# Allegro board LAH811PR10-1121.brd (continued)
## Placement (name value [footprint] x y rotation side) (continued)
CW123  0.1U_0201_10V6K  [C_0201]  260.14 11.98 0 top
CW125  0.1U_0201_10V6K  [C_0201]  260.19 13.37 90 top
CW126  1U_0201_6.3V6M  [C_0201]  260.77 13.37 90 top
CW223  100P_0201_50V8J  [C_0201]  266.52 15.92 0 top
CW225  100P_0201_50V8J  [C_0201]  23.99 25.91 90 bottom
CW226  100P_0201_50V8J  [C_0201]  265.2 17.52 0 top
CW227  100P_0201_50V8J  [C_0201]  24.88 26.5 270 bottom
CW228  0.1U_0201_10V6K  [C_0201]  267.91 9.82 180 top
CZ1  1U_0201_6.3V6M  [C_0201]  91.25 66.06 0 bottom
CZ2  0.1U_0201_10V6K  [C_0201]  125.03 66.46 180 top
CZ3  10U_0402_10V6M  [C_0402]  107.28 72.51 0 bottom
D1  -  [BAT54CW_SOT323-3]  100.02 69.64 90 bottom
D2  -  [BAT54CW_SOT323-3]  205.09 17.49 0 bottom
D3  -  [BAT54CW_SOT323-3]  201.89 22.93 0 bottom
D12  -  [RB751V40_SC76-2]  232.33 6.14 180 bottom
D13  AZ5B75-01B.R7G_CSP0603P2Y2  [AZ5B75-01BPR7G_CSP0603P2Y2]  264.38 42.44 180 bottom
D14  AZ5B75-01B.R7G_CSP0603P2Y2  [AZ5B75-01BPR7G_CSP0603P2Y2]  265.06 42.44 0 bottom
D16  -  [TVNST52302AB0_SOT523-3]  269.89 42.87 270 bottom
D20  -  [RB751S40T1G_SOD523-2]  187.08 29.18 180 top
D21  -  [RB751S40T1G_SOD523-2]  181.8 40.61 90 bottom
D23  -  [BAT54CW_SOT323-3]  200.94 14.89 180 bottom
D75  PESD5V0H1BSF_SOD962-2-2  [ESD101-B1-02ELS_TSSLP-2-4-2]  10.43 69.33 180 bottom
D76  PESD5V0H1BSF_SOD962-2-2  [ESD101-B1-02ELS_TSSLP-2-4-2]  13.68 70.55 180 top
D77  PESD5V0H1BSF_SOD962-2-2  [ESD101-B1-02ELS_TSSLP-2-4-2]  11.06 69.33 0 bottom
D78  PESD5V0H1BSF_SOD962-2-2  [ESD101-B1-02ELS_TSSLP-2-4-2]  12.28 70.55 0 top
D79  PESD5V0H1BSF_SOD962-2-2  [ESD101-B1-02ELS_TSSLP-2-4-2]  10.38 70.55 180 top
D80  PESD5V0H1BSF_SOD962-2-2  [ESD101-B1-02ELS_TSSLP-2-4-2]  13.68 70.55 180 bottom
D81  PESD5V0H1BSF_SOD962-2-2  [ESD101-B1-02ELS_TSSLP-2-4-2]  11.01 70.55 0 top
D82  PESD5V0H1BSF_SOD962-2-2  [ESD101-B1-02ELS_TSSLP-2-4-2]  12.28 70.55 0 bottom
D83  PESD5V0H1BSF_SOD962-2-2  [ESD101-B1-02ELS_TSSLP-2-4-2]  279.34 67.71 90 bottom
D84  PESD5V0H1BSF_SOD962-2-2  [ESD101-B1-02ELS_TSSLP-2-4-2]  280.51 61.92 90 top
D85  PESD5V0H1BSF_SOD962-2-2  [ESD101-B1-02ELS_TSSLP-2-4-2]  279.34 67.07 270 bottom
D86  PESD5V0H1BSF_SOD962-2-2  [ESD101-B1-02ELS_TSSLP-2-4-2]  280.51 63.31 270 top
D87  PESD5V0H1BSF_SOD962-2-2  [ESD101-B1-02ELS_TSSLP-2-4-2]  280.48 67.71 90 top
D88  PESD5V0H1BSF_SOD962-2-2  [ESD101-B1-02ELS_TSSLP-2-4-2]  280.51 61.92 90 bottom
D89  PESD5V0H1BSF_SOD962-2-2  [ESD101-B1-02ELS_TSSLP-2-4-2]  280.48 67.07 270 top
D90  PESD5V0H1BSF_SOD962-2-2  [ESD101-B1-02ELS_TSSLP-2-4-2]  280.51 63.31 270 bottom
D116  RB751S40T1G_SOD523-2  [RB520SM-30T2R_EMD2-2]  199.94 21.73 270 bottom
D132  -  [RB751V40_SC76-2]  71.38 6.16 0 bottom
D407  AZ5B75-01B.R7G_CSP0603P2Y2  [AZ5B75-01BPR7G_CSP0603P2Y2]  12.54 67.8 270 bottom
D408  AZ5B75-01B.R7G_CSP0603P2Y2  [AZ5B75-01BPR7G_CSP0603P2Y2]  12.54 68.86 270 bottom
D409  AZ5B75-01B.R7G_CSP0603P2Y2  [AZ5B75-01BPR7G_CSP0603P2Y2]  11.01 76.59 90 top
D410  AZ5B75-01B.R7G_CSP0603P2Y2  [AZ5B75-01BPR7G_CSP0603P2Y2]  11.01 75.44 90 top
D411  AZ5B75-01B.R7G_CSP0603P2Y2  [AZ5B75-01BPR7G_CSP0603P2Y2]  10.94 74.68 0 top
D412  AZ5B75-01B.R7G_CSP0603P2Y2  [AZ5B75-01BPR7G_CSP0603P2Y2]  11.33 68.52 180 top
D413  AZ5B75-01B.R7G_CSP0603P2Y2  [AZ5B75-01BPR7G_CSP0603P2Y2]  10.06 68.52 180 top
D414  AZ5B75-01B.R7G_CSP0603P2Y2  [AZ5B75-01BPR7G_CSP0603P2Y2]  11.01 78.12 270 top
D415  AZ5B75-01B.R7G_CSP0603P2Y2  [AZ5B75-01BPR7G_CSP0603P2Y2]  280.48 65.26 90 bottom
D416  AZ5B75-01B.R7G_CSP0603P2Y2  [AZ5B75-01BPR7G_CSP0603P2Y2]  280.48 64.18 90 bottom
D417  AZ5B75-01B.R7G_CSP0603P2Y2  [AZ5B75-01BPR7G_CSP0603P2Y2]  281.35 64.59 270 top
D418  AZ5B75-01B.R7G_CSP0603P2Y2  [AZ5B75-01BPR7G_CSP0603P2Y2]  281.35 65.67 270 top
D419  AZ5B75-01B.R7G_CSP0603P2Y2  [AZ5B75-01BPR7G_CSP0603P2Y2]  276.57 57.09 90 bottom
D420  AZ5B75-01B.R7G_CSP0603P2Y2  [AZ5B75-01BPR7G_CSP0603P2Y2]  279.24 66.24 180 top
D421  AZ5B75-01B.R7G_CSP0603P2Y2  [AZ5B75-01BPR7G_CSP0603P2Y2]  278.86 63.7 0 top
D422  AZ5B75-01B.R7G_CSP0603P2Y2  [AZ5B75-01BPR7G_CSP0603P2Y2]  276.57 58.23 90 bottom
D438  -  [RB751S40T1G_SOD523-2]  175.05 10.71 180 top
D459  AZ4520-01F.R7G_DFN1610P2E2  [AZ4520-01FPR7G_DFN1610P2E2]  11.8 64.97 0 bottom
D460  AZ4520-01F.R7G_DFN1610P2E2  [AZ4520-01FPR7G_DFN1610P2E2]  281.65 60.04 90 bottom
D461  SDM2U30CSP-7B  [NSR20F30NXT5G_DSN2-2]  31.73 27.17 0 bottom
D462  SDM2U30CSP-7B  [NSR20F30NXT5G_DSN2-2]  259.67 29.55 180 top
D465  PESD5V0H1BSF_SOD962-2-2  [ESD101-B1-02ELS_TSSLP-2-4-2]  127.22 61.49 90 top
D466  PESD5V0H1BSF_SOD962-2-2  [ESD101-B1-02ELS_TSSLP-2-4-2]  126.58 65.58 0 top
D468  -  [RB751S40T1G_SOD523-2]  172.34 51.38 0 top
D469  -  [LNZ8F6V2T5G_SOD882-2-X]  59.15 12.01 45 bottom
D470  -  [LNZ8F6V2T5G_SOD882-2-X]  228.77 16.63 90 bottom
D471  PESD5V0H1BSF_SOD962-2-2  [ESD101-B1-02ELS_TSSLP-2-4-2]  126.07 62.76 0 top
D474  -  [RB751S40T1G_SOD523-2]  173.48 9.44 0 top
D475  -  [RB751S40T1G_SOD523-2]  173.48 8.17 0 top
D481  -  [RB751V40_SC76-2]  222.92 13.51 0 bottom
D482  -  [TVNST52302AB0_SOT523-3]  197.19 5.11 270 bottom
D483  -  [TVNST52302AB0_SOT523-3]  197.28 2.62 270 bottom
D484  AZ5B75-01B.R7G_CSP0603P2Y2  [AZ5B75-01BPR7G_CSP0603P2Y2]  158.33 65.09 180 top
D485  AZ5B75-01B.R7G_CSP0603P2Y2  [AZ5B75-01BPR7G_CSP0603P2Y2]  159.09 65.09 0 top
D486  PESD5V0H1BSF_SOD962-2-2  [ESD101-B1-02ELS_TSSLP-2-4-2]  128.17 62.53 180 top
D487  -  [RB751S40T1G_SOD523-2]  173.18 11.96 180 top
DA1  -  [ESD207-B1-02EL_TSLP-2-19-2]  276.19 66.24 0 bottom
DA3  -  [ESD207-B1-02EL_TSLP-2-19-2]  274.59 61.66 270 bottom
DA4  -  [ESD207-B1-02EL_TSLP-2-19-2]  270.6 61.66 270 bottom
DA5  -  [ESD207-B1-02EL_TSLP-2-19-2]  266.41 61.69 270 bottom
DA8  AZ4A24-01F.R7G_DFN0603P2Y2  [AZ4A24-01FPR7G_DFN0603P2Y2]  20.03 32.23 90 top
DA9  AZ4A24-01F.R7G_DFN0603P2Y2  [AZ4A24-01FPR7G_DFN0603P2Y2]  20.03 34.48 270 top
DA10  -  [RB751S40T1G_SOD523-2]  266.66 54.81 90 top
DA11  AZ5125-01H.R7G_SOD523-2  [AZ5125-01HPR7G_SOD523-2]  255.61 60.9 180 bottom
DA13  -  [ESD207-B1-02EL_TSLP-2-19-2]  276.17 69.33 180 bottom
DA14  AZ4A24-01F.R7G_DFN0603P2Y2  [AZ4A24-01FPR7G_DFN0603P2Y2]  268.82 33.87 270 bottom
DA15  AZ4A24-01F.R7G_DFN0603P2Y2  [AZ4A24-01FPR7G_DFN0603P2Y2]  268.82 31.22 90 bottom
DA16  -  [ESD207-B1-02EL_TSLP-2-19-2]  24.1 27.32 0 bottom
DA17  -  [ESD207-B1-02EL_TSLP-2-19-2]  23.2 25.72 270 bottom
DA18  -  [ESD207-B1-02EL_TSLP-2-19-2]  266.72 17.67 0 top
DA19  -  [ESD207-B1-02EL_TSLP-2-19-2]  259.55 9.92 180 top
DC1  RB751S40T1G_SOD523-2  [RB520SM-30T2R_EMD2-2]  175.34 31.39 270 bottom
DC2  RB751S40T1G_SOD523-2  [RB520SM-30T2R_EMD2-2]  176.62 29.15 90 bottom
DE1  -  [RB520SM-30T2R_EMD2-2]  190.06 2.72 90 top
DE3  -  [RB520SM-30T2R_EMD2-2]  191.78 2.93 90 top
DR1  0_0402_5%  [R_0402]  248.43 9.95 0 bottom
DR2  0_0402_5%  [R_0402]  248.43 10.74 0 bottom
DR3  0_0402_5%  [R_0402]  268.25 10.71 180 top
DR6  0_0402_5%  [R_0402]  267.33 14.44 0 top
DR7  0_0402_5%  [R_0402]  267.33 15.26 0 top
DR8  0_0402_5%  [R_0402]  264.83 16.83 270 top
DR9  0_0402_5%  [R_0402]  268.25 11.52 180 top
DR10  0_0402_5%  [R_0402]  263.31 16.6 270 top
DR11  0_0402_5%  [R_0402]  262.55 16.54 270 top
DR12  0_0402_5%  [R_0402]  268.26 13.63 180 top
DR13  0_0402_5%  [R_0402]  245.35 10.05 0 bottom
DR14  33_0402_1%  [R_0402]  265.85 20.08 270 top
DR15  33_0402_1%  [R_0402]  266.69 20.08 270 top
DR16  33_0402_1%  [R_0402]  259.42 15.33 0 top
DR17  33_0402_1%  [R_0402]  258.61 12.18 90 top
DR18  0_0402_5%  [R_0402]  255.74 22.95 270 bottom
DR19  0_0402_5%  [R_0402]  256.53 22.95 270 bottom
DT1  -  [1N4148WS-L_SOD323-2]  28.28 63.57 0 bottom
DT2  -  [1N4148WS-L_SOD323-2]  282.51 52.75 90 bottom
DV11  RB751S40T1G_SOD523-2  [RB520SM-30T2R_EMD2-2]  108.9 68.06 270 bottom
DV12  RB751S40T1G_SOD523-2  [RB520SM-30T2R_EMD2-2]  114.64 68.13 90 bottom
DZ3  -  [RB751S40T1G_SOD523-2]  244.48 8.96 0 bottom
DZ4  -  [RB751S40T1G_SOD523-2]  244.45 11.07 0 bottom
F1  0.5A_65V_T0603FF0500TM  [F_T0603FF0500TM]  162.7 65.73 180 top
F2  0.5A_32V_0438.500WR  [F_0438P500WR]  256.43 42.82 270 bottom
F3  3A_32V_F0603FA3000V032T  [F_F0603FA3000V032T]  96.64 71.94 270 bottom
F5  0.5A_65V_T0603FF0500TM  [F_T0603FF0500TM]  160.67 62.98 90 top
F6  0.5A_65V_T0603FF0500TM  [F_T0603FF0500TM]  165.95 62.58 90 top
FD1  -  [FIDUCIAL_C40M80]  19.39 61.66 0 top
FD2  -  [FIDUCIAL_C40M80]  272.71 24.71 0 top
FD3  -  [FIDUCIAL_C40M80]  42.74 9.82 180 bottom
FD4  -  [FIDUCIAL_C40M80]  257.75 67.58 180 bottom
FD5  -  [FIDUCIAL_C40M80]  272.66 8.45 180 bottom
H1  -  [H_1P6]  11.6 82.85 45 top
H2  H_3P6  [H_3P6-G]  4.85 67.7 90 top
H4  H_2P6  [H_2P6-G]  40.46 27.84 0 top
H5  H_3P6  [H_3P6-G]  19.9 2.8 0 top
H6  H_3P6  [H_3P6-G]  88.95 55.22 0 top
H7  H_3P6  [H_3P6-G]  203.95 55.22 0 top
H8  H_3P6  [H_3P6-G]  273 2.8 0 top
H9  H_2P6  [H_2P6-G]  254.6 32.34 0 top
H10  H_3P6  [H_3P6-G]  287.06 54.64 0 top
H14  -  [H_1P3N]  1.55 44.9 0 top
H15  PAD~50  [TPC20]  196.27 10.71 180 bottom
H16  PAD~50  [TPC20]  261.39 2.73 180 bottom
H18  PAD~50  [TPC20]  120.35 66.4 180 bottom
H19  PAD~50  [TPC20]  146.45 65.7 180 bottom
H20  PAD~50  [TPC20]  172.55 66.4 180 bottom
HCPU1  -  [H_3P3]  114.31 63.52 0 top
HCPU2  -  [H_3P3]  113.87 36.32 0 top
HCPU3  -  [H_3P3]  179.02 36.32 0 top
HCPU4  -  [H_3P3]  178.59 63.52 0 top
HSSD1  -  [H_3P3]  105.29 17.15 0 top
JAPS1  ACES_50506-01841-P01  [ACES_50506-01841-P01_18P]  194.27 21.35 90 top
JBATT1  DEREN_40-42507-01001RHF_10P  [DEREN_40-42507-01001RHF_10P-T]  44.03 24.06 225 bottom
JDB1  ACES_50521-01041-P01  [ACES_50521-01041-P01_10P]  34.4 33.76 90 top
JDB2  ACES_50521-01041-P01  [ACES_50521-01041-P01_10P]  279 46.08 90 top
JDB3  JXT_FP241AH-006GAAM  [JXT_FP241AH-006GAAM_6P]  33.66 56.48 90 top
JDB4  JXT_FP241AH-006GAAM  [JXT_FP241AH-006GAAM_6P]  278.39 40.47 90 top
JDEBUG1  ACES_50521-01041-P01  [ACES_50521-01041-P01_10P]  193.4 44.68 90 top
JDEBUG2  ACES_50521-01041-P01  [ACES_50521-01041-P01_10P]  151.01 6.07 0 top
JDEG1  -  [ACES_50521-01041-P01_10P]  238.61 13.78 0 bottom
JEDP1  I-PEX_20698-042E-01  [I-PEX_20698-042E-01_42P-T]  134.7 64.33 180 bottom
JFAN1  ACES_50224-00401-001  [ACES_50224-00401-001_4P]  65.95 6.77 0 bottom
JFAN2  ACES_50224-00401-001  [ACES_50224-00401-001_4P]  232.15 7.98 0 bottom
JFP1  TWVM_FPC0510-08RC-TAGHA  [TWVM_FPC0510-08RC-TAGHA_8P]  256.95 36.94 270 bottom
JHP1  UNIMI_FCECBE015  [UNIMI_FCECBE015_6P-T]  268.2 66.61 180 bottom
JIO1  HRS_FH35C-45S-0P3SHW(50)  [HRS_FH35C-45S-0P3SHW-50_45P]  215.15 8.23 180 bottom
JMIPI60  SAMTE_QSH-030-01-L-D-A  [SAMTE_QSH-030-01-H-D-A_60P-T]  90.88 65.78 0 top
JNGFF1  LOTES_APCI0146-P004A  [LOTES_APCI0146-P004A_75P]  188.83 7.9 90 bottom
JP1  T-SOL_5-751903001000-6  [T-SOL_5-751903001000-6_22P-T]  0.5 48.05 90 bottom
JSPI1  -  [ACES_50521-01041-P01_10P]  193.66 35.53 270 bottom
JSPK1  ACES_50208-0040C-P03  [ACES_50208-0040C-P03_4P-T]  19.24 32.6 90 bottom
JSPK2  ACES_50208-0040C-P03  [ACES_50208-0040C-P03_4P-T]  270.67 32.8 270 bottom
JTAG2  @SHORT PADS~D  [SHORTPADS]  189.57 8.88 0 top
JTP1  ACES_50506-00841-P01  [ACES_50506-00841-P01_8P]  206.21 10.06 180 bottom
JUART1  CVILU_CI1804M1VRA-NH  [CVILU_CI1804M1VRA-NH_4P]  179.49 42.3 270 top
JUFC1  I-PEX_20698-042E-01  [I-PEX_20698-042E-01_42P-T]  165.2 64.33 180 bottom
JUSBC1  DEREN_560Q10-002H  [DEREN_560Q10-002H_24P-T]  9.67 74.08 90 bottom
JUSBC2  DEREN_560Q10-002H  [DEREN_560Q10-002H_24P-T]  283.22 68.15 270 bottom
JWLA1  TWVM_FPC0511-04RC-TAGHT  [TWVM_FPC0511-04RC-TAGHT_4P]  264.88 13.15 270 bottom
JWLA2  TWVM_FPC0511-04RC-TAGHT  [TWVM_FPC0511-04RC-TAGHT_4P]  21.24 30.01 180 bottom
L12  BLM15PX330SN1D_2P  [MURAT_BLM15PX330SN1D_2P]  275.65 68.18 270 bottom
L15  BLM15PX330SN1D_2P  [MURAT_BLM15PX330SN1D_2P]  271.57 61.64 0 bottom
L71  BLM15PX330SN1D_2P  [MURAT_BLM15PX330SN1D_2P]  265.7 15.93 90 top
L72  BLM15PX330SN1D_2P  [MURAT_BLM15PX330SN1D_2P]  267.44 16.73 180 top
L73  BLM15PX330SN1D_2P  [MURAT_BLM15PX330SN1D_2P]  25.03 23.9 90 bottom
L74  BLM15PX330SN1D_2P  [MURAT_BLM15PX330SN1D_2P]  24.14 23.9 90 bottom
LA1  HCB2012KF-600T30  [TAI-T_HCB2012KF-121T50_2P]  257.27 62.93 270 bottom
LA18  BLM15AX700SN1D_2P  [MURAT_BLM15AX700SN1D_2P]  263.74 66.87 270 bottom
LA19  BLM15AX700SN1D_2P  [MURAT_BLM15AX700SN1D_2P]  263.74 65.09 270 bottom
LA20  BLM15AX700SN1D_2P  [MURAT_BLM15AX700SN1D_2P]  23.93 27.45 180 top
LA21  BLM15AX700SN1D_2P  [MURAT_BLM15AX700SN1D_2P]  25.74 27.4 90 top
LA22  BLM15AX700SN1D_2P  [MURAT_BLM15AX700SN1D_2P]  267.37 31.44 270 top
LA23  BLM15AX700SN1D_2P  [MURAT_BLM15AX700SN1D_2P]  269.94 37.36 90 top
LC1  0.68UH_UHP252012NF-R68M_3A_20%  [TAI-T_UHP252012NF-R68M_2P]  174.77 49.5 0 bottom
LC2  BLM18EG221TN1D_2P~D  [MURAT_BLM18EG221SN1D_2P]  175.43 44.7 180 bottom
LED1  HT-F196BP5_WHITE  [LED_HT-F196BP5_2P]  252.87 22.43 90 bottom
LED2  HT-F196BP5_WHITE  [LED_HT-F196BP5_2P]  251.63 22.43 90 bottom
LT3  BLM18KG331SN1D_2P  [MURAT_BLM18KG331SN1D_2P]  25.89 46.05 0 bottom
LT5  0.68UH_MLV-YT10NR68N-M1L_2.7A_30%  [MAG_MLV-YT10NR68N-M1L_2P]  265.01 47.85 180 bottom
LT8  0.68UH_MLV-YT10NR68N-M1L_2.7A_30%  [MAG_MLV-YT10NR68N-M1L_2P]  22.47 53.1 270 bottom
LT9  HCB2012KF-800T50_2P  [TAI-T_HCB2012KF-121T50_2P]  61.85 9.69 315 bottom
LT10  HCB2012KF-800T50_2P  [TAI-T_HCB2012KF-121T50_2P]  237.73 6.18 90 bottom
LT11  HCB2012KF-800T50_2P  [TAI-T_HCB2012KF-121T50_2P]  28.04 25.23 0 bottom
LT12  HCB2012KF-800T50_2P  [TAI-T_HCB2012KF-121T50_2P]  262.36 25.8 180 top
LT13  HCB2012KF-800T50_2P  [TAI-T_HCB2012KF-121T50_2P]  28.04 23.46 0 bottom
LT14  HCB2012KF-800T50_2P  [TAI-T_HCB2012KF-121T50_2P]  262.36 27.58 180 top
LT15  BLM18KG331SN1D_2P  [MURAT_BLM18KG331SN1D_2P]  258.41 48.58 0 top
LV1  BLM15PX221SN1D_2P  [MURAT_BLM15PX221SN1D_2P]  135.74 64.28 180 top
ML1  HCM1012GH900BP_4P  [INPAQ_HCM1012GH900BP_4P]  256.93 19.83 0 top
ML6  HCM1012GH900BP_4P  [INPAQ_HCM1012GH900BP_4P]  14.81 68.39 180 bottom
ML7  HCM1012GH900BP_4P  [INPAQ_HCM1012GH900BP_4P]  11.75 72.44 90 top
ML16  HCM1012GH900BP_4P  [INPAQ_HCM1012GH900BP_4P]  278.22 64.61 0 bottom
ML17  HCM1012GH900BP_4P  [INPAQ_HCM1012GH900BP_4P]  279.13 65.15 0 top
ML18  HCM1012GH900BP_4P  [INPAQ_HCM1012GH900BP_4P]  267.96 43.07 180 bottom
NOREF  -  []  202.91 4.77 0 top
NOREF#2  -  []  83.96 11.28 0 top
NOREF#3  -  []  102.5 47.26 90 top
NOREF#4  -  []  170.78 -19.36 0 top
NOREF#5  -  []  214.09 4.07 0 top
NOREF#6  -  []  104.74 -40.32 0 top
NOREF#7  -  []  195.49 59.15 0 top
NOREF#8  -  []  22.37 13.2 0 top
NOREF#9  -  []  116.1 40.52 0 top
NOREF#10  -  []  110.78 1.58 180 bottom
PC132  0.01UF_0402_25V7K  [C_0402]  61.35 17.85 0 bottom
PC133  100P_0201_50V8J  [C_0201]  61.69 17.09 0 bottom
PC134  1000P_0201_50V7K  [C_0201]  52.23 19.55 45 bottom
PC135  100P_0201_50V8J  [C_0201]  51.75 20 45 bottom
PC200  0.1U_0402_25V6  [C_0402]  78.96 11.04 90 bottom
PC201  0.1U_0402_25V6  [C_0402]  72.47 14.17 180 bottom
PC202  2200P_0402_50V7K  [C_0402]  78.96 13.86 270 bottom
PC203  10U_0603_25V6M  [C_0603-H1_2]  80.05 14 270 bottom
PC204  10U_0603-H1_2_25V6M  [C_0603-H1_2]  72.28 13.21 270 bottom
PC207  10U_0603-H1_2_25V6M  [C_0603-H1_2]  78.03 18.76 180 bottom
PC210  4.7U_0402_16V6M  [C_0402]  36.77 6.11 90 bottom
PC211  0.1U_0402_25V6  [C_0402]  40.68 4.03 90 top
PC212  1U_0402_25V6K  [C_0402]  34.58 2.91 270 bottom
PC213  1U_0402_25V6K  [C_0402]  37.02 2.91 0 bottom
PC214  10U_0603_25V6M  [C_0603]  93.69 28.2 90 top
PC215  10U_0603_25V6M  [C_0603]  90.07 20.64 0 top
PC216  10U_0603_25V6M  [C_0603]  93.42 25.32 0 bottom
PC217  10U_0603-H1_2_25V6M  [C_0603-H1_2]  90.07 21.91 0 bottom
PC218  33U_B3_16VM_R45M  [C_B3]  80.72 25.17 315 bottom
PC219  33U_B3_16VM_R45M  [C_B3]  83.04 27.49 315 bottom
PC221  10U_0603-H1_2_25V6M  [C_0603-H1_2]  91.78 25.53 270 bottom
PC222  10U_0603-H1_2_25V6M  [C_0603-H1_2]  90.07 20.64 0 bottom
PC223  0.1U_0402_25V6  [C_0402]  93.38 26.41 0 bottom
PC224  2200P_0402_50V7K  [C_0402]  94.44 25.17 0 top
PC225  0.47U_0603_25V7K  [C_0603]  39 8.69 270 bottom
PC226  1U_0402_25V6K  [C_0402]  37.68 5.22 90 bottom
PC227  4.7U_0603_25VAK  [C_0603]  36.54 4.62 180 bottom
PC228  2.2U_0402_6.3V6M  [C_0402]  35.27 9.83 180 top
PC229  2.2U_0402_6.3V6M  [C_0402]  33.31 4.64 0 bottom
PC230  0.47U_0603_25V7K  [C_0603]  33.53 11.66 135 bottom
PC231  10U_0603_25V6M  [C_0603]  72.78 17.61 270 bottom
PC232  10U_0603_25V6M  [C_0603]  71.51 16.6 270 bottom
PC233  4700P_0402_25V7K  [C_0402]  63.03 12.64 180 bottom
PC234  2200P_0402_50V7K  [C_0402]  58.78 13.22 225 bottom
PC235  2.2U_0402_25V6M  [C_0402]  32.19 11.45 135 bottom
PC236  680P_0402_50V7K  [C_0402]  79.59 8.58 90 bottom
PC237  680P_0402_50V7K  [C_0402]  92.6 13.66 0 bottom
PC238  1U_0402_25V6K  [C_0402]  33.94 17.61 270 bottom
PC239  1U_0402_25V6K  [C_0402]  33.68 15.81 180 bottom
PC240  0.22U_0402_25V6K  [C_0402]  32.86 16.69 90 bottom
PC241  560P_0402_50V7K  [C_0402]  30.35 8.37 90 bottom
PC243  0.01U_0402_16V7K  [C_0402]  29.48 8.41 180 bottom
PC244  0.1U_0402_25V6  [C_0402]  28.7 9.82 180 bottom
PC245  0.1U_0402_25V6  [C_0402]  30.39 10.66 90 bottom
PC246  15U_B2_25VM_R100M  [C_B2]  74.59 13.58 90 bottom
PC247  15U_B2_25VM_R100M  [C_B2]  77.11 16.55 0 bottom
PC249  1U_0201_6.3V6M  [C_0201]  36.37 9.06 0 top
PC335  1U_0402_16V6K  [C_0402]  218.45 20.06 270 bottom
PC336  2200P_0402_50V7K  [C_0402]  203.8 26.87 225 bottom
PC337  0.1U_0402_25V6  [C_0402]  216.32 15.49 0 bottom
PC338  22U_0603_6.3V6M  [C_0603-H1_2]  206.21 32.2 45 bottom
PC339  2200P_0402_50V7K  [C_0402]  207.86 30.17 45 bottom
PC340  2200P_0402_50V7K  [C_0402]  216.32 16.43 0 bottom
PC341  680P_0603_50V7K  [C_0603]  206.59 21.4 135 bottom
PC342  4.7U_0402_6.3V6M  [C_0402]  211.77 18.79 0 bottom
PC343  0.22U_0402_16V7K  [C_0402]  214.8 21.99 225 bottom
PC344  22U_0603_6.3V6M  [C_0603-H1_2]  204.81 34.36 45 bottom
PC345  10U_0603_25V6M  [C_0603-H1_2]  212.56 15.63 90 bottom
PC346  22U_0603_6.3V6M  [C_0603-H1_2]  205.7 33.47 45 bottom
PC347  22U_0603_6.3V6M  [C_0603-H1_2]  202.4 28.9 225 bottom
PC348  22U_0603_6.3V6M  [C_0603-H1_2]  206.85 30.93 45 bottom
PC349  10U_0603_25V6M  [C_0603-H1_2]  215.42 16.35 180 bottom
PC350  22U_0603_6.3V6M  [C_0603-H1_2]  203.31 28.05 225 bottom
PC351  22U_0603_6.3V6M  [C_0603-H1_2]  204.06 25.32 270 bottom
PC400  0.22U_0402_16V7K  [C_0402]  21.67 15.53 180 bottom
PC401  0.1U_0402_25V6  [C_0402]  31.32 14.01 270 bottom
PC402  2200P_0402_50V7K  [C_0402]  29.89 15.43 90 bottom
PC403  10U_0603_25V6M  [C_0603-H1_2]  30.42 17.47 180 bottom
PC404  10U_0603_25V6M  [C_0603-H1_2]  30.27 14.01 270 bottom
PC405  220P_0201_25V7K  [C_0201]  25.24 19.12 0 bottom
PC406  22U_0603_6.3V6M  [C_0603-H0_8]  25.08 3.97 270 top
PC407  22U_0603_6.3V6M  [C_0603-H0_8]  27.53 3.97 270 top
PC408  22U_0603_6.3V6M  [C_0603-H0_8]  25.11 3.5 270 bottom
PC409  22U_0603_6.3V6M  [C_0603-H0_8]  26.31 3.96 270 top
PC410  22U_0603_6.3V6M  [C_0603-H1_2]  26.17 9.85 90 bottom
PC412  22U_0603_6.3V6M  [C_0603-H1_2]  24.95 9.85 90 bottom
PC414  2.2U_0402_6.3V6M  [C_0402]  28.75 11.48 180 bottom
PC415  680P_0603_50V7K  [C_0603]  21.74 19.37 0 top
PC416  0.22U_0402_16V7K  [C_0402]  274.08 25.34 90 bottom
PC417  0.1U_0402_25V6  [C_0402]  271.62 15.69 0 bottom
PC418  2200P_0402_50V7K  [C_0402]  271.62 16.58 0 bottom
PC419  10U_0603_25V6M  [C_0603-H1_2]  270.65 16.45 180 bottom
PC420  10U_0603_25V6M  [C_0603-H1_2]  270.65 15.23 180 bottom
PC421  220P_0201_25V7K  [C_0201]  274.38 19.58 270 top
PC422  22U_0603_6.3V6M  [C_0603-H1_2]  261.53 24.82 180 bottom
PC423  22U_0603_6.3V6M  [C_0603-H0_8]  261.53 26.06 180 bottom
PC424  22U_0603_6.3V6M  [C_0603-H1_2]  261.48 23.55 180 bottom
PC425  22U_0603_6.3V6M  [C_0603-H1_2]  263.84 24 270 bottom
PC426  22U_0603_6.3V6M  [C_0603-H1_2]  262.62 23.39 270 bottom
PC428  22U_0603_6.3V6M  [C_0603-H1_2]  261.53 27.31 180 bottom
PC430  2.2U_0402_6.3V6M  [C_0402]  268.31 18.46 90 bottom
PC431  680P_0603_50V7K  [C_0603]  271.1 19.55 180 top
PC432  33U_B3_16VM_R45M  [C_B3]  31.88 19.81 180 bottom
PC433  33U_B3_16VM_R45M  [C_B3]  267.4 16.4 180 bottom
PC500  0.22U_0402_16V7K  [C_0402]  195.61 60.25 315 bottom
PC501  10U_0603_25V6M  [C_0603]  201.62 63.75 315 top
PC502  10U_0603_25V6M  [C_0603]  201.44 63.57 315 bottom
PC503  0.1U_0402_25V6  [C_0402]  202.6 63.97 315 bottom
PC504  2200P_0402_25V7K  [C_0402]  202.03 64.58 135 bottom
PC505  220P_0201_25V7K  [C_0201]  197.93 65.37 135 bottom
PC506  22U_0603_6.3V6M  [C_0603]  194.81 47.92 180 bottom
PC507  22U_0603_6.3V6M  [C_0603]  197.16 45.48 0 bottom
PC508  22U_0603_6.3V6M  [C_0603]  194.74 46.68 180 bottom
PC509  22U_0603_6.3V6M  [C_0603]  197.16 46.7 0 bottom
PC510  2.2U_0402_6.3V6M  [C_0402]  197.38 62.61 45 bottom
PC512  680P_0603_50V7K  [C_0603]  191.98 51.21 270 bottom
PC600  4.7U_0402_6.3V6M  [C_0402]  113.33 2.56 0 top
PC700  0.22U_0402_25V6K  [C_0402]  99.71 17.09 0 bottom
PC701  680P_0603_50V7K  [C_0603]  100.04 21.15 0 bottom
PC702  220P_0402_50V8J  [C_0402]  102.2 13.35 270 bottom
PC703  22U_0603_6.3V6M  [C_0603-H1_2]  95.3 23.74 180 bottom
PC704  2200P_0402_50V7K  [C_0402]  98.67 27.2 90 bottom
PC705  22U_0603_6.3V6M  [C_0603-H1_2]  101.44 23.69 270 bottom
PC706  22U_0603_6.3V6M  [C_0603-H1_2]  100.17 23.69 270 bottom
PC707  22U_0603_6.3V6M  [C_0603-H1_2]  96.31 27.25 90 bottom
PC708  2200P_0402_50V7K  [C_0402]  95.21 27.12 90 bottom
PC709  10U_0603_25V6M  [C_0603-H1_2]  99.21 9.85 180 bottom
PC710  0.1U_0402_25V6  [C_0402]  100.6 9.72 0 bottom
PC711  2200P_0402_25V7K  [C_0402]  100.6 8.7 0 bottom
PC713  0.22U_0402_10V6K  [C_0402]  95.67 14.65 180 bottom
PC714  0.22U_0402_10V6K  [C_0402]  95.67 13.76 180 bottom
PC715  1U_0402_16V6K  [C_0402]  95.59 11.42 90 bottom
PC750  10U_0603_25V6M  [C_0603-H1_2]  99.21 8.58 180 bottom
PC751  22U_0603_6.3V6M  [C_0603-H1_2]  97.58 27.25 90 bottom
PC801  0.22U_0402_16V7K  [C_0402]  200.67 42.79 0 bottom
PC802  10U_0603_25V6M  [C_0603]  202.88 48.35 0 bottom
PC803  10U_0603_25V6M  [C_0603]  202.88 48.36 0 top
PC804  0.1U_0402_25V6  [C_0402]  203.21 49.73 0 bottom
PC805  2200P_0402_25V7K  [C_0402]  203.21 49.73 0 top
PC806  22U_0603_6.3V6M  [C_0603]  203.8 38.04 0 bottom
PC807  22U_0603_6.3V6M  [C_0603]  203.8 39.31 0 bottom
PC808  22U_0603_6.3V6M  [C_0603]  201.83 41.11 180 bottom
PC809  22U_0603_6.3V6M  [C_0603]  204.43 36.75 0 bottom
PC810  2.2U_0402_6.3V6M  [C_0402]  200.75 45.26 180 bottom
PC811  680P_0402_50V7K  [C_0402]  204.56 41.9 90 top
PC812  220P_0402_50V8J  [C_0402]  199.84 44.9 0 top
PC900  1U_0402_16VAK  [C_0402]  192.43 70.74 45 bottom
PC901  1U_0402_25V6K  [C_0402]  188.98 68.58 135 bottom
PC902  10U_0603_16VAM  [C_0603-H1_2]  195.81 70.11 135 bottom
PC903  33U_B3_16VM_R45M  [C_B3]  202.85 71.16 90 bottom
PC904  10U_0603_16VAM  [C_0603-H1_2]  196.52 69.41 315 bottom
PC905  10U_0603_25V6M  [C_0603]  195.8 70.11 135 top
PC906  10U_0603_25V6M  [C_0603]  196.69 70.96 135 top
PC907  10U_0603_25V6M  [C_0603]  196.51 69.41 315 top
PC908  10U_0603_16VAM  [C_0603-H1_2]  196.69 70.94 135 bottom
PC909  1U_0402_16VAK  [C_0402]  198.9 69.79 270 bottom
PC910  1U_0402_25V6K  [C_0402]  194.97 62.75 315 bottom
PC911  0.1U_0201_25V6K  [C_0201]  195.91 64.98 315 bottom
PC912  680P_0603_50V7K  [C_0603]  187.87 71.01 45 bottom
PC1000  150U_B3_6.3VM_R35M  [C_TEPSLB30J157M-35-8R]  184.47 56.89 225 bottom
PC1001  150U_B3_6.3VM_R35M  [C_TEPSLB30J157M-35-8R]  186.75 54.6 225 bottom
PC1004  22U_0603_6.3V6M  [C_0603-H0_8]  162.59 53.66 0 top
PC1005  22U_0603_6.3V6M  [C_0603-H0_8]  138.43 52.9 180 top
PC1006  22U_0603_6.3V6M  [C_0603-H0_8]  142.58 55.41 0 top
PC1007  22U_0603_6.3V6M  [C_0603-H0_8]  141.03 61.17 90 top
PC1008  22U_0603_6.3V6M  [C_0603-H0_8]  127.96 52.56 180 top
PC1009  22U_0603_6.3V6M  [C_0603-H0_8]  162.59 52.45 0 top
PC1010  22U_0603_6.3V6M  [C_0603-H0_8]  159.2 52.45 270 top
PC1011  22U_0603_6.3V6M  [C_0603-H0_8]  160.63 54.46 90 top
PC1012  22U_0603_6.3V6M  [C_0603-H0_8]  139.26 60 270 top
PC1013  22U_0603_6.3V6M  [C_0603-H0_8]  136.93 61.35 180 bottom
PC1014  10U_0402_6.3V6M  [C_0402]  138.75 54.56 90 top
PC1015  10U_0402_6.3V6M  [C_0402]  157.19 59.26 270 top
PC1016  10U_0402_6.3V6M  [C_0402]  158.27 60.76 90 top
PC1017  10U_0402_6.3V6M  [C_0402]  155.78 54.44 90 top
PC1018  10U_0402_6.3V6M  [C_0402]  159.57 54.4 90 top
PC1019  10U_0402_6.3V6M  [C_0402]  160.28 52.51 270 top
PC1020  10U_0402_6.3V6M  [C_0402]  156.71 54.43 90 top
PC1021  10U_0402_6.3V6M  [C_0402]  139.72 54.57 90 top
PC1022  10U_0402_6.3V6M  [C_0402]  140.07 62.55 0 bottom
PC1023  10U_0402_6.3V6M  [C_0402]  141.63 54.57 90 top
PC1024  22U_0603_6.3V6M  [C_0603-H0_8]  161.35 52.44 270 top
PC1025  22U_0603_6.3V6M  [C_0603-H0_8]  139.84 61.14 90 top
PC1026  47U_0603_6.3V6M  [C_0603-H1_2]  182.3 59.63 225 bottom
PC1027  22U_0603_6.3V6M  [C_0603-H0_8]  158.5 54.46 90 top
PC1028  22U_0603_6.3V6M  [C_0603-H0_8]  155.09 60.6 180 top
PC1029  22U_0603_6.3V6M  [C_0603-H0_8]  156.33 52.2 270 top
PC1030  47U_0603_6.3V6M  [C_0603-H1_2]  183.17 58.77 225 bottom
PC1031  10U_0402_6.3V6M  [C_0402]  156.3 59.26 270 top
PC1032  10U_0402_6.3V6M  [C_0402]  137.89 61.23 90 top
PC1033  10U_0402_6.3V6M  [C_0402]  157.39 52.51 270 top
PC1034  10U_0402_6.3V6M  [C_0402]  138.77 61.23 90 top
PC1035  10U_0402_6.3V6M  [C_0402]  129.76 53.15 0 top
PC1036  10U_0402_6.3V6M  [C_0402]  140.63 54.54 90 top
PC1037  10U_0402_6.3V6M  [C_0402]  157.38 60.76 90 top
PC1038  10U_0402_6.3V6M  [C_0402]  159.09 59.26 270 top
PC1039  10U_0402_6.3V6M  [C_0402]  137 61.23 90 top
PC1040  1U_0201_6.3V6M  [C_0201]  138.56 51.96 270 top
PC1041  1U_0201_6.3V6M  [C_0201]  138.39 61.07 90 bottom
PC1042  1U_0201_6.3V6M  [C_0201]  156.56 53 180 top
PC1043  1U_0201_6.3V6M  [C_0201]  137.73 61.07 90 bottom
PC1044  1U_0201_6.3V6M  [C_0201]  156.55 53.57 180 top
PC1045  0.1U_0201_6.3V6K  [C_0201]  158.18 52.64 270 top
PC1046  0.1U_0201_6.3V6K  [C_0201]  159.03 60.86 90 top
PC1047  0.1U_0201_6.3V6K  [C_0201]  157.52 54.31 90 top
PC1048  0.1U_0201_6.3V6K  [C_0201]  138.02 54.75 90 top
PC1049  0.1U_0201_6.3V6K  [C_0201]  129 53.03 90 top
PC1051  15P_0201_50V8J  [C_0201]  161.56 54.6 90 top
PC1052  15P_0201_50V8J  [C_0201]  155.56 59.07 270 top
PC1053  15P_0201_50V8J  [C_0201]  156.6 60.88 90 top
PC1054  15P_0201_50V8J  [C_0201]  141.39 59.78 0 top
PC1055  15P_0201_50V8J  [C_0201]  141.39 60.37 0 top
PC1100  2.2U_0402_6.3V6M  [C_0402]  94.4 60.5 180 bottom
PC1101  4.7U_0402_6.3V6M  [C_0402]  94.35 59.33 180 bottom
PC1102  1000P_0402_25V8J  [C_0402]  94.4 62.23 180 bottom
PC1103  150P_0402_50V8J  [C_0402]  98.82 65.68 180 bottom
PC1104  0.1U_0402_25V7K  [C_0402]  94.4 63.31 180 bottom
PC1105  390P_0402_50V7K  [C_0402]  99.68 64.99 90 bottom
PC1106  0.1U_0201_25V6K  [C_0201]  105.65 60.28 180 bottom
PC1107  330P_0402_50V8J  [C_0402]  102.25 62.17 0 bottom
PC1108  2.2U_0402_6.3V6M  [C_0402]  102.25 60.39 0 bottom
PC1200  0.1U_0402_25V6  [C_0402]  92.72 47.82 0 bottom
PC1201  1000P_0402_50V7K  [C_0402]  92.72 46.93 0 bottom
PC1202  1U_0402_16VAK  [C_0402]  98.13 44.7 90 bottom
PC1203  10U_0603_25V6M  [C_0603]  92.44 44.45 270 top
PC1204  10U_0603_16VAM  [C_0603-H1_2]  92.44 44.45 270 bottom
PC1206  1U_0402_16VAK  [C_0402]  96.18 37.28 180 bottom
PC1207  0.22U_0603_25V7K  [C_0603]  97.18 37.41 0 bottom
PC1208  680P_0603_50V7K  [C_0603]  104.42 29.28 0 bottom
PC1209  33U_B3_16VM_R45M  [C_B3]  89.47 33.02 180 bottom
PC1210  33U_B3_16VM_R45M  [C_B3]  89.12 36.03 90 bottom
PC1211  33U_B3_16VM_R45M  [C_B3]  90.94 46.55 180 bottom
PC1212  33U_B3_16VM_R45M  [C_B3]  89.11 43.33 270 bottom
PC1213  0.1U_0402_25V6  [C_0402]  92.72 38.17 0 bottom
PC1214  1000P_0402_50V7K  [C_0402]  92.72 37.28 0 bottom
PC1215  1U_0402_16VAK  [C_0402]  98.13 35.18 90 bottom
PC1216  10U_0603_16VAM  [C_0603-H1_2]  92.42 34.55 270 bottom
PC1217  10U_0603_25V6M  [C_0603]  92.42 34.55 270 top
PC1219  1U_0402_16VAK  [C_0402]  96.18 46.93 180 bottom
PC1220  0.22U_0603_25V7K  [C_0603]  97.18 47.06 0 bottom
PC1221  680P_0603_50V7K  [C_0603]  104.48 37.98 90 bottom
PC1222  10U_0603_25V6M  [C_0603]  91.15 44.46 270 top
PC1223  10U_0603_25V6M  [C_0603]  91.2 34.55 270 top
PC1300  150U_B3_6.3VM_R35M  [C_TEPSLB30J157M-35-8R]  110.4 32.2 270 bottom
PC1301  150U_B3_6.3VM_R35M  [C_TEPSLB30J157M-35-8R]  113.49 53.41 90 bottom
PC1302  150U_B3_6.3VM_R35M  [C_TEPSLB30J157M-35-8R]  116.8 53.43 90 bottom
PC1304  22U_0603_6.3V6M  [C_0603-H1_2]  118.31 50.18 90 bottom
PC1305  22U_0603_6.3V6M  [C_0603-H1_2]  116.93 46.11 270 bottom
PC1306  22U_0603_6.3V6M  [C_0603-H1_2]  118.2 46.11 270 bottom
PC1307  22U_0603_6.3V6M  [C_0603-H0_8]  116.93 46.11 270 top
PC1308  22U_0603_6.3V6M  [C_0603-H1_2]  119.47 46.11 270 bottom
PC1309  22U_0603_6.3V6M  [C_0603-H0_8]  118.31 50.18 90 top
PC1310  22U_0603_6.3V6M  [C_0603-H0_8]  119.47 46.11 270 top
PC1311  22U_0603_6.3V6M  [C_0603-H0_8]  118.2 46.11 270 top
PC1312  10U_0402_6.3V6M  [C_0402]  121.78 50.45 270 top
PC1313  10U_0402_6.3V6M  [C_0402]  154.4 44.7 90 top
PC1314  10U_0402_6.3V6M  [C_0402]  122.14 47.68 0 top
PC1315  10U_0402_6.3V6M  [C_0402]  124.95 50.41 270 top
PC1316  10U_0402_6.3V6M  [C_0402]  150.2 55.19 90 top
PC1317  10U_0402_6.3V6M  [C_0402]  147.92 55.19 90 top
PC1318  10U_0402_6.3V6M  [C_0402]  132.68 53.15 180 top
PC1319  10U_0402_6.3V6M  [C_0402]  126.4 46.74 90 top
PC1320  47U_0603_6.3V6M  [C_0603-H1_2]  119.54 50.18 90 bottom
PC1321  22U_0603_6.3V6M  [C_0603-H0_8]  119.54 50.18 90 top
PC1322  1U_0402_6.3V6K  [C_0402]  159.22 44.7 90 top
PC1323  1U_0402_6.3V6K  [C_0402]  152.74 54.52 90 top
PC1324  1U_0201_6.3V6M  [C_0201]  127.8 46.12 0 top
PC1325  1U_0201_6.3V6M  [C_0201]  153.51 54.42 90 top
PC1326  1U_0201_6.3V6M  [C_0201]  127.83 47.51 0 top
PC1327  1U_0201_6.3V6M  [C_0201]  127.85 50.05 0 top
PC1328  1U_0201_6.3V6M  [C_0201]  127.85 48.81 0 top
PC1329  0.1U_0201_6.3V6K  [C_0201]  132.8 51.63 270 top
PC1330  0.1U_0201_6.3V6K  [C_0201]  131.53 51.63 270 top
PC1331  0.1U_0201_6.3V6K  [C_0201]  155.13 52.7 270 top
PC1332  0.1U_0201_6.3V6K  [C_0201]  132.17 51.63 270 top
PC1333  0.1U_0201_6.3V6K  [C_0201]  155.72 43.85 90 top
PC1334  150U_B3_6.3VM_R35M  [C_TEPSLB30J157M-35-8R]  106.67 48.61 180 bottom
PC1335  15P_0201_50V8J  [C_0201]  159.91 43.81 0 top
PC1336  150U_B3_6.3VM_R35M  [C_TEPSLB30J157M-35-8R]  106.64 51.35 90 bottom
PC1337  150U_B3_6.3VM_R35M  [C_TEPSLB30J157M-35-8R]  109.92 51.33 90 bottom
PC1338  15P_0201_50V8J  [C_0201]  117.25 50.54 90 top
PC1339  15P_0201_50V8J  [C_0201]  115.63 50.54 90 top
PC1340  15P_0201_50V8J  [C_0201]  135.32 52.82 0 top
PC1341  33U_B3_16VM_R45M  [C_B3]  101.33 50.59 90 bottom
PC1342  33U_B3_16VM_R45M  [C_B3]  98.11 50.59 90 bottom
PC1343  33U_B3_16VM_R45M  [C_B3]  94.88 50.59 90 bottom
PC1344  15P_0201_50V8J  [C_0201]  133.71 53.43 90 top
PC1345  15P_0201_50V8J  [C_0201]  137.47 45.08 270 top
PC1346  15P_0201_50V8J  [C_0201]  135.85 45.08 270 top
PC1347  15P_0201_50V8J  [C_0201]  134.22 45.08 270 top
PC1348  15P_0201_50V8J  [C_0201]  133 45.08 270 top
PC1349  15P_0201_50V8J  [C_0201]  131.38 45.08 270 top
PC1350  15P_0201_50V8J  [C_0201]  129.75 45.08 270 top
PC1351  33U_B3_16VM_R45M  [C_B3]  189 52.32 225 bottom
PC1352  33U_B3_16VM_R45M  [C_B3]  182.58 66.48 45 bottom
PD104  -  [TVNST52302AB0_SOT523-3]  36.55 24 225 bottom
PD105  -  [TVNST52302AB0_SOT523-3]  35.71 19.97 315 bottom
PD200  -  [SMF4L22A_SOD123FL2]  75.17 6.19 90 bottom
PD201  -  [RB520SM-30T2R_EMD2-2]  39.12 3.01 0 top
PD202  -  [RB520SM-30T2R_EMD2-2]  39.12 1.82 0 top
PD600  -  [RB520SM-30T2R_EMD2-2]  117.34 2.31 90 top
PD601  -  [RB520SM-30T2R_EMD2-2]  118.53 2.31 90 top
PD602  -  [RB520SM-30T2R_EMD2-2]  119.73 2.31 90 top
PD603  -  [RB520SM-30T2R_EMD2-2]  116.12 4.03 270 top
PD604  -  [BAT54HT1G_SOD323-2]  72.12 8.56 90 bottom
PJP301  PAD-OPEN 4X4M  [JUMP_43X118]  201.39 32.33 180 bottom
PJP400  PAD-OPEN 4X4M  [JUMP_43X118]  25.6 6.63 0 bottom
PJP401  PAD-OPEN 4X4M  [JUMP_43X118]  264.58 29.62 90 bottom
PJP500  PAD-OPEN 4X4M  [JUMP_43X118]  195.95 43.32 270 bottom
PJP700  -  [JUMP_43X79]  100.42 26.23 0 bottom
PJP800  -  [JUMP_43X79]  201.63 38.08 180 bottom
PJTAG1  @SHORT PADS~D  [SHORTPADS]  96.86 20.16 0 top
PJTAG2  @SHORT PADS~D  [SHORTPADS]  96.86 13.4 0 top
PJTAG3  @SHORT PADS~D  [SHORTPADS]  96.86 17.47 0 top
PJTAG4  @SHORT PADS~D  [SHORTPADS]  96.81 21.51 0 top
PJTAG7  @SHORT PADS~D  [SHORTPADS]  96.89 16.12 0 top
PJTAG8  @SHORT PADS~D  [SHORTPADS]  96.89 14.75 0 top
PJTAG9  @SHORT PADS~D  [SHORTPADS]  96.89 18.81 0 top
PL102  HCB2012KF-800T50_2P  [TAI-T_HCB2012KF-121T50_2P]  58.73 14.7 180 bottom
PL103  HCB2012KF-800T50_2P  [TAI-T_HCB2012KF-121T50_2P]  56.15 18.36 180 bottom
PL104  HCB2012KF-800T50_2P  [TAI-T_HCB2012KF-121T50_2P]  58.19 16.53 180 bottom
PL200  1UH_1277AS-H-1R0N-P2_3.3A_30%  [TOKO_1277AS-H-1R0N-P2_2P]  77.69 7.48 90 bottom
PL250  2.2UH_MHCB06030-2R2M-C1L_10A_20%  [CHILI_MHCB06030-2R2M-C1L_2P]  84.01 11 0 bottom
PL308  1UH_MLD-06CZH1R0M-N1L_11.3A_20%  [MAG_MLD-06CZH1R0M-N1L_2P]  211.8 22.17 135 bottom
PL400  HCB2012KF-800T50_2P  [TAI-T_HCB2012KF-121T50_2P]  32.73 23.7 270 bottom
PL401  1.5UH_MMD-05CZN1R5M-V1L_7.2A_20%  [MAG_MMD-05CZN1R5M-V1L_2P]  21.37 13.27 270 bottom
PL402  HCB2012KF-800T50_2P  [TAI-T_HCB2012KF-121T50_2P]  244.97 7.68 270 bottom
PL403  1.5UH_MMD-05CZN1R5M-V1L_7.2A_20%  [MAG_MMD-05CZN1R5M-V1L_2P]  271.66 24.71 180 bottom
PL404  HCB2012KF-800T50_2P  [TAI-T_HCB2012KF-121T50_2P]  34.54 23.7 270 bottom
PL405  HCB2012KF-800T50_2P  [TAI-T_HCB2012KF-121T50_2P]  246.8 7.68 270 bottom
PL555  1UH_MHCI06012-1R0M-R8A_6A_20%  [CHILI_MHCI06012-1R0M-R8A_2P]  196.17 56.49 270 bottom
PL701  HCB2012KF-800T50_2P  [TAI-T_HCB2012KF-121T50_2P]  99.32 7.05 0 bottom
PL702  0.68UH_MMD-05CZ-R68M-X2L_8.5A_20%  [MAG_MMD-05CZ-R68M-X2L_2P]  96.74 17.31 90 bottom
PL801  1UH_HEI322512A-1R0M-Q8_3.7A_20%  [CHILI_HEI322512A-1R0M-Q8_2P]  203.95 43.25 270 bottom
PL900  0.15UH_MMD-05AB-R15M-T1L_12A_20%  [MAG_MMD-05AB-R15M-T1L_2P]  188.32 66 225 bottom
PL901  0.15UH_MMD-05AB-R15M-T1L_12A_20%  [MAG_MMD-05AB-R15M-T1L_2P]  192.26 62.06 225 bottom
PL902  HCB2012KF-800T50_2P  [TAI-T_HCB2012KF-121T50_2P]  204.05 67.42 90 bottom
PL903  HCB2012KF-800T50_2P  [TAI-T_HCB2012KF-121T50_2P]  202.15 67.42 90 bottom
PL1200  0.15UH_TMPC0603H-R15M_37A_20%  [TAI-T_TMPC0603H-R15M_4P]  101.13 33.88 0 bottom
PL1201  0.15UH_TMPC0603H-R15M_37A_20%  [TAI-T_TMPC0603H-R15M_4P]  101.15 43.38 0 bottom
PL1202  HCB2012KF-800T50_2P  [TAI-T_HCB2012KF-121T50_2P]  88.23 28.3 90 bottom
PL1203  HCB2012KF-800T50_2P  [TAI-T_HCB2012KF-121T50_2P]  86.32 28.3 90 bottom
PL1204  HCB2012KF-800T50_2P  [TAI-T_HCB2012KF-121T50_2P]  90.13 28.3 90 bottom
PL1205  HCB2012KF-800T50_2P  [TAI-T_HCB2012KF-121T50_2P]  92.04 28.3 90 bottom
PQ100  -  [2N7002KDW_SOT363-6]  102.96 9.97 0 bottom
PQ201  -  [AON6962_DFN5X6D-8-7]  79.29 15.32 90 bottom
PQ202  -  [AON7405_DFN8-5]  63.14 16 270 bottom
PQ203  -  [AON6962_DFN5X6D-8-7]  86.91 15.39 90 bottom
PQ205  -  [L2N7002WT1G_SC70-3]  30.06 2.63 270 top
PQ600  -  [L2N7002WT1G_SC70-3]  105.96 2.66 90 top
PR100  0_0402_5%  [R_0402]  104.36 9.21 90 top
PR101  200K_0201_5%  [R_0201]  103.9 10.99 0 bottom
PR102  0_0402_5%  [R_0402]  102.83 9.21 90 top
PR103  200K_0201_5%  [R_0201]  105.12 9.72 270 top
PR104  0_0402_5%  [R_0402]  103.6 8.45 0 top
PR105  0_0402_5%  [R_0402]  103.6 9.21 90 top
PR110  0_0402_5%  [R_0402]  36.89 19.17 45 bottom
PR185  1M_0402_1%  [R_0402]  52.75 19.07 45 bottom
PR195  100_0402_1%  [R_0402]  39.15 22.03 135 bottom
PR196  100_0402_1%  [R_0402]  38.58 21.46 135 bottom
PR197  0_0402_5%  [R_0402]  38.16 20.72 135 bottom
PR200  0.01_1206_1%  [R_1206_4P-D]  77.43 11.1 90 bottom
PR201  442K_0402_1%  [R_0402]  39.08 5.22 270 top
PR202  1_0402_1%  [R_0402]  35.42 2 90 bottom
PR203  1_0402_1%  [R_0402]  36.21 2 90 bottom
PR204  100K_0402_1%  [R_0402]  38.17 5.18 90 top
PR205  2.2_0603_5%  [R_0603]  37.81 7.04 90 bottom
PR206  2_1206_5%  [R_1206]  27.84 31.06 0 top
PR207  4.7_0402_5%  [R_0402]  35.68 9.01 270 top
PR208  2_1206_5%  [R_1206]  37.49 2.51 180 top
PR210  2.2_0603_5%  [R_0603]  34.26 12.66 135 bottom
PR211  0.005_1206_1%  [R_1206_4P-D]  77.03 21.72 225 bottom
PR212  0_0201_5%  [R0201_0OHM]  34.59 4.65 90 top
PR213  0_0402_5%  [R0402_0OHM]  33.91 4.26 90 top
PR214  0_0402_5%  [R0402_0OHM]  33.13 4.26 90 top
PR215  4.7_1206_5%  [R_1206]  81.12 11.44 270 bottom
PR216  4.7_1206_5%  [R_1206]  93.05 9.78 90 bottom
PR217  75_0402_5%  [R_0402]  32.35 4.27 90 top
PR218  0_0402_5%  [R0402_0OHM]  31.75 12.11 90 top
PR219  100K_0402_5%  [R_0402]  30.6 4.26 90 top
PR220  0_0402_5%  [R0402_0OHM]  31.57 4.27 90 top
PR221  1_0402_1%  [R_0402]  34.51 19.32 270 bottom
PR222  1_0402_1%  [R_0402]  33.75 19.32 270 bottom
PR223  0_0402_5%  [R0402_0OHM]  33.76 2.81 270 top
PR224  100K_0402_5%  [R_0402]  29.4 5.99 0 bottom
PR225  154K_0402_1%  [R_0402]  29.81 1.69 180 top
PR226  93.1K_0402_1%  [R_0402]  30.37 6.8 180 bottom
PR227  1M_0402_5%  [R_0402]  32.99 1.89 90 top
PR229  0_0201_5%  [R0201_0OHM]  31.04 11.74 180 top
PR230  1K_0402_1%  [R_0402]  31.87 8.2 180 top
PR231  499_0402_1%  [R_0402]  30.37 7.56 180 bottom
PR232  10K_0201_5%  [R_0201]  30.44 12.34 0 top
PR233  0_0402_5%  [R0402_0OHM]  31.86 9.14 180 top
PR234  0_0402_5%  [R0402_0OHM]  31.85 10.04 180 top
PR236  100_0402_1%  [R_0402]  29.57 10.68 90 bottom
PR301  4.7_0805_5%  [R_0805]  208.5 19.25 135 bottom
PR302  0_0402_5%  [R0402_0OHM]  219.47 17.29 180 bottom
PR303  2.2K_0402_1%  [R_0402]  219.47 16.5 180 bottom
PR304  3.3_0603_1%  [R_0603]  216.48 21.82 135 bottom
PR305  0_0402_5%  [R0402_0OHM]  211.77 17.95 0 bottom
PR306  0_0402_5%  [R0402_0OHM]  219.24 15.61 180 bottom
PR307  0.01_0603_1%  [R_0603]  213.53 13.2 90 bottom
PR308  0.01_0603_1%  [R_0603]  212.28 13.2 90 bottom
PR400  0_0402_5%  [R0402_0OHM]  28.18 14.29 90 top
PR401  90.9K_0201_1%  [R_0201]  25.24 17.85 270 bottom
PR403  0_0603_5%  [R_0603]  23.98 15.68 180 bottom
PR404  26.1K_0402_1%  [R_0402]  27.65 18.18 270 bottom
PR406  274K_0402_1%  [R_0402]  26 17.26 90 bottom
PR407  499_0402_1%  [R_0402]  26.81 18.18 270 bottom
PR408  150K_0201_5%  [R_0201]  28.3 10.6 0 bottom
PR409  13.3K_0402_1%  [R_0402]  27.72 18.97 180 bottom
PR410  4.7_0805_5%  [R_0805]  18.92 19.63 0 top
PR411  0_0402_5%  [R_0402]  26.8 19.74 0 bottom
PR412  0_0402_5%  [R0402_0OHM]  273.39 15.33 90 bottom
PR413  0_0201_5%  [R0201_0OHM]  274.38 20.72 90 top
PR415  0_0603_5%  [R_0603]  274.11 23.02 90 bottom
PR416  26.1K_0402_1%  [R_0402]  274.31 18.87 90 bottom
PR418  274K_0402_1%  [R_0402]  273.67 21.28 270 top
PR419  499_0402_1%  [R_0402]  273.7 19.6 270 top
PR420  150K_0201_5%  [R_0201]  267.55 19.06 270 bottom
PR421  13.3K_0402_1%  [R_0402]  274.31 20.57 90 bottom
PR422  4.7_0805_5%  [R_0805]  272.43 21.16 270 top
PR423  0_0402_5%  [R_0402]  274.31 18.13 270 bottom
PR501  499_0402_1%  [R_0402]  198.42 65.87 315 bottom
PR502  40.2K_0402_1%  [R_0402]  199.63 64.7 225 bottom
PR503  150K_0201_5%  [R_0201]  196.61 62.38 315 bottom
PR504  20K_0402_1%  [R_0402]  198.38 64.81 225 bottom
PR506  4.7_0805_5%  [R_0805]  191.74 53.98 270 bottom
PR507  0_0603_5%  [R_0603]  197.32 60.19 135 bottom
PR509  100K_0201_5%  [R_0201]  203.64 61.38 45 top
PR510  274K_0402_1%  [R_0402]  192.23 55.2 90 bottom
PR511  0.01_0603_1%  [R_0603]  203.93 65.8 270 bottom
PR600  100K_0402_5%  [R_0402]  107.1 2.36 0 top
PR601  100K_0402_5%  [R_0402]  107.1 3.14 0 top
PR602  549K_0402_1%  [R_0402]  114.22 3.41 180 top
PR603  100K_0402_5%  [R_0402]  103.03 3.91 270 top
PR604  100K_0402_5%  [R_0402]  102.24 2.96 270 top
PR605  1M_0402_5%  [R_0402]  113.29 1.71 0 top
PR606  100K_0402_5%  [R_0402]  111.93 5.15 180 top
PR607  0_0402_5%  [R_0402]  111.93 4.39 180 top
PR608  0_0402_5%  [R_0402]  107.09 3.92 0 top
PR700  0_0603_5%  [R_0603]  99.59 15.94 0 bottom
PR701  4.7_0805_5%  [R_0805]  100.32 18.23 90 bottom
PR702  0_0402_5%  [R_0402]  101.89 13.28 180 top
PR703  16.9K_0402_1%  [R_0402]  103.09 13.4 270 bottom
PR704  20K_0402_1%  [R_0402]  101.31 12.46 90 bottom
PR706  0_0402_5%  [R0402_0OHM]  101.94 11.5 180 top
PR707  0_0402_5%  [R_0402]  101.31 11.63 0 bottom
PR708  0_0402_5%  [R_0402]  95.59 10.56 270 bottom
PR709  0_0402_5%  [R0402_0OHM]  101.94 12.39 180 top
PR801  0_0603_5%  [R_0603]  200.71 44.19 180 bottom
PR802  150K_0201_5%  [R_0201]  205.33 44.83 270 bottom
PR803  0_0402_5%  [R0402_0OHM]  199.84 44.01 0 top
PR804  4.7_0603_5%  [R_0603]  203.42 43.31 270 top
PR805  0_0402_5%  [R_0402]  200.75 45.79 180 top
PR806  0.01_0603_1%  [R_0603]  200.93 49.73 0 bottom
PR900  5.1_0402_1%  [R_0402]  192.44 72.02 225 bottom
PR901  150K_0201_1%  [R_0201]  196.77 65.01 135 bottom
PR902  0_0603_5%  [R_0603]  190.7 67.04 135 bottom
PR903  100_0201_1%  [R_0201]  189.24 70.86 45 bottom
PR904  0_0603_5%  [R_0603]  193.27 64.44 315 bottom
PR906  100_0201_1%  [R_0201]  190.13 71.74 45 bottom
PR907  0_0201_5%  [R_0201]  189.65 69.08 135 bottom
PR908  90.9K_0201_1%  [R_0201]  190.16 69.59 135 bottom
PR910  4.7_0805_5%  [R_0805]  186.08 68.92 45 bottom
PR912  0_0201_5%  [R0201_0OHM]  195.88 64.12 135 bottom
PR915  0_0402_5%  [R0402_0OHM]  190.79 69.98 135 bottom
PR916  0_0402_5%  [R0402_0OHM]  191.42 70.61 135 bottom
PR1100  6.19K_0402_1%  [R_0402]  92.67 62.25 270 bottom
PR1101  49.9K_0402_1%  [R_0402]  94.4 61.35 180 bottom
PR1102  4.7_0402_5%  [R_0402]  95.16 58.13 90 bottom
PR1103  0_0201_5%  [R0201_0OHM]  91.99 60.8 90 bottom
PR1104  2M_0402_1%  [R_0402]  92.67 63.24 90 bottom
PR1106  133K_0402_1%  [R_0402]  94.4 64.2 180 bottom
PR1107  1.5K_0402_1%  [R_0402]  96.84 66.69 270 bottom
PR1108  1.5K_0402_1%  [R_0402]  96.08 66.69 270 bottom
PR1109  10K_0201_5%  [R_0201]  120.66 56.46 0 top
PR1110  0_0402_5%  [R0402_0OHM]  96.08 65.04 270 bottom
PR1111  10K_0201_5%  [R_0201]  96.1 56.29 90 bottom
PR1112  10K_0201_5%  [R_0201]  96.67 56.29 90 bottom
PR1113  10K_0201_5%  [R_0201]  98.83 56.29 90 bottom
PR1114  1.91K_0402_1%  [R_0402]  100.36 56.1 90 bottom
PR1115  0_0201_5%  [R0201_0OHM]  95.53 56.88 270 bottom
PR1116  0_0402_5%  [R0402_0OHM]  96.84 65.04 270 bottom
PR1117  806_0402_1%  [R_0402]  98.79 64.81 180 bottom
PR1118  0_0402_5%  [R_0402]  97.37 57.04 270 bottom
PR1119  100_0201_1%  [R_0201]  100.52 66.91 270 bottom
PR1120  4.99K_0402_1%  [R_0402]  99.71 66.74 180 bottom
PR1121  0_0402_5%  [R_0402]  98.13 57.04 270 bottom
PR1122  0_0402_5%  [R0402_0OHM]  100.52 65.68 270 bottom
PR1123  75_0402_5%  [R_0402]  99.53 57.04 270 bottom
PR1124  0_0402_5%  [R0402_0OHM]  101.28 65.68 270 bottom
PR1125  0_0201_5%  [R0201_0OHM]  101.06 56.81 270 bottom
PR1126  100_0201_1%  [R_0201]  101.28 66.91 270 bottom
PR1127  45.3_0402_1%  [R_0402]  104.81 57.47 180 bottom
PR1128  100_0402_1%  [R_0402]  104.81 58.49 180 bottom
PR1129  45.3_0402_1%  [R_0402]  104.81 59.5 180 bottom
PR1130  0_0402_5%  [R0402_0OHM]  102.25 57.47 0 bottom
PR1131  0_0402_5%  [R0402_0OHM]  102.25 58.49 0 bottom
PR1132  0_0402_5%  [R0402_0OHM]  102.25 59.5 0 bottom
PR1133  53.6K_0402_1%  [R_0402]  102.25 63.06 0 bottom
PR1134  61.9K_0402_1%  [R_0402]  102.25 61.28 0 bottom
PR1200  0_0402_5%  [R0402_0OHM]  95.26 38.17 0 bottom
PR1201  4.7_1206_5%  [R_1206]  100.48 29.35 0 bottom
PR1202  0_0402_5%  [R0402_0OHM]  95.26 47.82 0 bottom
PR1203  4.7_1206_5%  [R_1206]  100.48 38.68 0 bottom
PR1204  0_0201_5%  [R0201_0OHM]  94.45 37.7 270 bottom
PR1205  0_0201_5%  [R0201_0OHM]  94.45 47.35 270 bottom
PR1300  1K_0402_5%  [R_0402]  154.45 52.63 270 top
PT200  PAD~D  [TPC12]  39.33 6.16 0 top
PU200  -  [ISL9538CHRTZ-T_TQFN32_4X4]  32.19 9.81 270 bottom
PU302  -  [NB680GD-Z_QFN12_2X3]  216.08 18.21 90 bottom
PU400  -  [NB502GQ-Z_QFN16_3X3]  27.83 14.91 180 bottom
PU401  -  [NB502GQ-Z_QFN16_3X3]  271.71 18.62 90 bottom
PU500  -  [NB691GG-Z_QFN11_2X2]  200.11 62.22 225 bottom
PU600  -  [SN74LVC1G123DCUR_VSSOP8]  109.24 3.34 270 top
PU700  -  [NB685GQ-Z_QFN16_3X3]  99.02 12.05 90 bottom
PU800  -  [NB691GG-Z_QFN11_2X2]  202.87 46.47 270 bottom
PU900  -  [MP2941BGL-Z_QFN19_3X4]  194.03 69.22 225 bottom
PU1100  MP2940AGRT-0015-Z_TQFN28_4X4  [MP2940AGRT-0010-Z_TQFN28_4X4-S]  97.1 62.86 270 bottom
PU1200  -  [MP86902-BGLT-Z_TQFN21-15_3X4]  96.34 34.96 180 bottom
PU1201  -  [MP86902-BGLT-Z_TQFN21-15_3X4]  96.34 44.62 180 bottom
Q3  -  [L2N7002WT1G_SC-70-3]  198.08 19.69 0 bottom
Q15  -  [AO6405_TSOP6]  90.19 69.93 90 bottom
Q16  -  [2N7002KDW_SOT363-6]  90.45 68.46 270 bottom
Q30  -  [PMDXB600UNE_DFN1010B-6]  183.2 29.49 0 top
Q124  -  [PMZ370UNE_DFN1006-3]  201.23 10.03 0 bottom
Q348  -  [L2N7002WT1G_SC-70-3]  203.09 18.79 90 bottom
Q349  PJ2301_SOT23-3  [LP2301ALT1G_SOT23-3]  198.08 28.03 0 bottom
Q350  -  [PMZ370UNE_DFN1006-3]  162.98 6.7 0 top
Q351  2N7002KDW 2N SOT-363-6  [L2N7002DW1T1G_SC88-6]  204.04 14.42 0 bottom
Q352  -  [PMDXB600UNE_DFN1010B-6]  192.37 7.16 180 bottom
QC2  -  [PMDXB600UNE_DFN1010B-6]  173.91 53.38 270 top
QC5  -  [2N7002KDW_SOT363-6]  189.97 73.64 90 bottom
QE3  -  [PMBT3904MB_SOT883B]  34.63 61.54 270 bottom
QE4  -  [PMBT3904MB_SOT883B]  135.88 43.5 90 top
QE8  -  [PMBT3904MB_SOT883B]  141.67 56.53 270 top
QE10  -  [PMBT3904MB_SOT883B]  104.23 11.75 0 bottom
QE14  -  [PMBT3904MB_SOT883B]  200.47 67.5 180 bottom
QE15  -  [L2N7002WT1G_SC-70-3]  155.99 30.29 270 bottom
QE16  -  [LMBT3904WT1G_SC70-3]  161.67 30.35 270 bottom
QE17  -  [PMBT3904MB_SOT883B]  138.86 12.27 0 top
QE18  -  [2N7002KDW_SOT363-6]  154.66 29.67 180 bottom
QE19  -  [L2N7002WT1G_SC-70-3]  206.29 16.99 270 bottom
QE23  -  [L2N7002WT1G_SC-70-3]  210.07 18.33 180 bottom
QE25  -  [LMBT3904WT1G_SC70-3]  222.94 15.52 90 bottom
QE26  -  [2N7002KDW_SOT363-6]  219.55 19.96 0 bottom
QF1  -  [PMZ370UNE_DFN1006-3]  262.17 42.54 0 bottom
QF3  -  [PMZ370UNE_DFN1006-3]  186.98 2.89 90 top
QM1  -  [2N7002KDW_SOT363-6]  178.78 52.14 90 bottom
QR1  -  [PMZ370UNE_DFN1006-3]  11.38 38.22 270 bottom
QT1  -  [PMZ370UNE_DFN1006-3]  25.24 58.96 0 top
QT2  -  [PMZ370UNE_DFN1006-3]  263.87 56.48 90 bottom
QV18  LMBT3906N3T5G_SOT883-3  [MMBT3906LP-7B_X1-DFN1006-3]  110.33 70.05 270 bottom
QV19  LMBT3904N3T5G_SOT883-3  [MMBT3904LP-7B_X1-DFN1006-3]  112.26 70.07 0 bottom
QV20  LMBT3906N3T5G_SOT883-3  [MMBT3906LP-7B_X1-DFN1006-3]  111.27 67.76 180 bottom
QV21  LMBT3904N3T5G_SOT883-3  [MMBT3904LP-7B_X1-DFN1006-3]  111.97 68.88 0 bottom
QW1  -  [PMZ370UNE_DFN1006-3]  264.58 19.58 90 bottom
QW2  -  [PMDXB600UNE_DFN1010B-6]  259.91 16.32 90 top
QZ10  -  [AO6405_TSOP6]  178.63 69.05 90 bottom
QZ11  -  [L2N7002WT1G_SC-70-3]  182.21 48.28 270 bottom
QZ20  -  [LMUN5111T1G_SC70-3]  219.6 13.94 270 bottom
R24  0_0603_5%  [R0603_0OHM]  105.07 72.47 270 bottom
R25  90.9K_0201_1%  [R_0201]  99.02 71.23 90 bottom
R29  100K_0201_5%  [R_0201]  91.42 66.67 0 bottom
R30  100K_0402_5%  [R_0402]  90.26 73.7 180 bottom
R31  100K_0201_5%  [R_0201]  203.01 16.65 90 bottom
R32  10K_0201_5%  [R_0201]  204.05 20.52 180 bottom
R36  10K_0201_1%  [R_0201]  71.6 7.28 0 bottom
R37  10K_0201_1%  [R_0201]  73.46 7.28 180 bottom
R38  10K_0201_1%  [R_0201]  70.32 6.2 270 bottom
R39  10K_0201_1%  [R_0201]  233.95 6.65 180 bottom
R40  10K_0201_1%  [R_0201]  230.19 7.26 0 bottom
R41  10K_0201_1%  [R_0201]  234.61 6.55 270 bottom
R54  0_0201_5%  [R_0201]  182.84 42.23 0 bottom
R81  0_0402_5%  [R_0402]  174.31 3.78 0 top
R87  0.01_0603_1%  [R_0603]  94.2 72.19 270 bottom
R112  51_0201_5%  [R_0201]  91.05 74.4 270 top
R113  0_0201_5%  [R_0201]  92.08 75.13 180 top
R114  0_0201_5%  [R_0201]  90.1 75.13 0 top
R123  0.01_0402_1%  [R_0402]  88.46 62.25 90 top
R137  10K_0201_5%  [R_0201]  89.8 75.13 270 bottom
R138  0_0402_5%  [R_0402]  109.77 71.37 270 top
R140  1K_0201_5%  [R_0201]  93.69 63.23 270 top
R141  1K_0201_5%  [R_0201]  94.32 63.23 270 top
R142  1K_0201_5%  [R_0201]  94.96 63.23 270 top
R143  1K_0201_5%  [R_0201]  95.59 63.23 270 top
R144  1K_0201_5%  [R_0201]  94.98 65.7 270 bottom
R145  1K_0201_5%  [R_0201]  97.88 63.28 270 top
R146  1K_0201_5%  [R_0201]  98.64 63.28 270 top
R147  1K_0201_5%  [R_0201]  100.04 63.23 270 top
R148  1K_0201_5%  [R_0201]  100.67 63.23 270 top
R149  1K_0201_5%  [R_0201]  101.31 63.23 270 top
R150  1K_0201_5%  [R_0201]  101.94 63.23 270 top
R151  1K_0201_5%  [R_0201]  102.58 63.23 270 top
R152  1K_0201_5%  [R_0201]  103.21 63.23 270 top
R153  1K_0201_5%  [R_0201]  103.85 63.23 270 top
R154  1K_0201_5%  [R_0201]  104.48 63.23 270 top
R155  1K_0201_5%  [R_0201]  105.12 63.23 270 top
R156  0_0201_5%  [R0201_0OHM]  89.42 73.82 90 top
R157  0_0201_5%  [R_0201]  110.33 69.04 270 top
R160  1K_0201_5%  [R_0201]  95.47 46.59 90 top
R161  1K_0201_5%  [R_0201]  96.03 46.66 90 top
R162  10K_0201_5%  [R_0201]  94.96 61.96 270 top
R163  10K_0201_5%  [R_0201]  95.59 61.96 270 top
R164  10K_0201_5%  [R_0201]  96.23 61.96 270 top
R165  10K_0201_5%  [R_0201]  97.88 62.01 270 top
R166  10K_0201_5%  [R_0201]  98.64 62.01 270 top
R167  10K_0201_5%  [R_0201]  100.04 61.96 270 top
R168  1K_0201_5%  [R_0201]  110.02 49.03 90 top
R169  1K_0201_5%  [R_0201]  110.66 49.03 90 top
R170  1K_0201_5%  [R_0201]  111.29 49.03 90 top
R171  10K_0201_5%  [R_0201]  102.58 61.96 270 top
R172  1K_0201_5%  [R_0201]  118.48 54.74 90 top
R173  1K_0201_5%  [R_0201]  119.11 54.74 90 top
R174  10K_0201_5%  [R_0201]  104.48 61.96 270 top
R175  10K_0201_5%  [R_0201]  105.12 61.96 270 top
R176  1K_0201_5%  [R_0201]  88.63 75.11 270 bottom
R178  10K_0201_5%  [R_0201]  106.39 61.37 90 top
R188  0_0201_5%  [R_0201]  92.42 62.64 90 top
R190  0_0201_5%  [R0201_0OHM]  89.88 63.23 270 top
R191  0_0201_5%  [R0201_0OHM]  90.51 61.96 270 top
R192  0_0201_5%  [R0201_0OHM]  91.78 63.23 270 top
R193  0_0201_5%  [R_0201]  105.75 63.23 270 top
R194  0_0201_5%  [R_0201]  106.39 63.23 270 top
R195  0_0201_5%  [R_0201]  107.02 63.23 270 top
R200  0_0402_5%  [R_0402]  188.41 46.45 270 bottom
R201  0_0201_5%  [R0201_0OHM]  88.84 73.82 90 top
R204  0_0603_5%  [R0603_0OHM]  182.21 48.46 90 top
R208  0_0201_5%  [R0201_0OHM]  263.08 43.15 270 bottom
R210  1K_0201_5%  [R_0201]  102.71 73.47 90 bottom
R211  0_0603_5%  [R0603_0OHM]  274.05 43.52 270 top
R213  0_0201_5%  [R0201_0OHM]  91.78 61.96 270 top
R216  0_0603_5%  [R0603_0OHM]  124.22 5.06 90 top
R220  100K_0201_5%  [R_0201]  103.77 68.76 270 bottom
R222  0_0603_5%  [R0603_0OHM]  264.76 2.25 90 bottom
R230  1K_0201_5%  [R_0201]  101.56 74.67 90 bottom
R231  1M_0402_5%  [R_0402]  92.19 73.04 180 bottom
R232  10K_0201_5%  [R_0201]  255.23 50.11 90 bottom
R236  0_0201_5%  [R_0201]  89.98 74.4 270 top
R237  100K_0201_5%  [R_0201]  128.59 61.87 270 top
R238  2.2K_0201_1%  [R_0201]  128.23 66.36 90 top
R239  2.2K_0201_1%  [R_0201]  127.6 66.36 90 top
R244  0_0201_5%  [R0201_0OHM]  89.24 63.23 270 top
R245  100K_0201_5%  [R_0201]  126.96 66.36 90 top
